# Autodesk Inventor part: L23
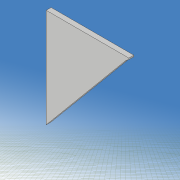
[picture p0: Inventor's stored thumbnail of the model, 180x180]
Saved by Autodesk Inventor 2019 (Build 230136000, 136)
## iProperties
Created: 2021-05
Part Number: L23
Material: 一般
Document SubType Name: Modeling
Designer: kikut
Density: 1 g/cm^3
Appearance: 既定
Mass: 0.00934248 g
Surface Area: 0.426451 cm^2
Volume: 0.00934248 cm^3
Author: kikut
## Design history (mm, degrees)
sketch "スケッチ1"
  geometry: L1 (80, 60)-(-80, 60); L2 (-80, 60)-(-80, -60); L3 (-80, -60)-(80, -60); L4 (80, -60)-(80, 60); L5 (80, 60)-(-80, -60); L6 (-80, 60)-(80, -60); 1 further point
  constraints: 12 end point, 2 midpoint, 2 parallel, 1 horizontal, 1 perpendicular
  dimensions: "d0" = 160 distance of L2.end L3.end; "d1" = 120 distance of L1.end L2.end
extrude "押し出し1" new body sketch "スケッチ1" stored distance "d2" = 0.6; taper "d3" = 0 deg
sketch "スケッチ2"
  geometry: L1 (-140, 0)-(140, 0) reference; L2 (0, -54)-(20, -30); L3 (0, 54)-(20, 30); L4 (0, -3)-(6.514, -3); L5 (6.514, -3)-(16, -6); L6 (16, -6)-(24, -3); L7 (24, -3)-(33.716, -3); L8 (0, 3)-(6.514, 3); L9 (6.514, 3)-(16, 6); L10 (16, 6)-(24, 3); L11 (24, 3)-(33.716, 3); L12 (0, -98)-(0, 98) reference; L13 (-100, -70)-(100, -70); L14 (100, -70)-(100, 70); L15 (100, 70)-(-100, 70); L16 (-100, 70)-(-100, -70); L17 (-100, -70)-(100, 70); L18 (100, -70)-(-100, 70); A1 r 60 centre (54.312, 28.5) between (0, 54) and (0, 3); A2 r 60 centre (54.312, -28.5) between (0, -3) and (0, -54); A3 r 18.111 centre (18, -12) between (20, -30) and (33.716, -3); A4 r 18.111 centre (18, 12) between (33.716, 3) and (20, 30); 1 further point
  constraints: 32 end point, 8 point on circle, 8 symmetric about line, 4 centre point, 3 horizontal, 2 collinear, 2 midpoint, 2 parallel, 1 perpendicular
  dimensions: "d5" = 60 radius of A1; "d6" = 6 distance of L8.start L4.start; "d7" = 108 distance of L3.start L2.start; "d8" = 0 horizontal distance of L3.start L8.start; "d9" = 60 distance of L3.end L2.end; "d10" = 0 horizontal distance of point (0, 0) L3.start; "d11" = 20 horizontal distance of L3.start L3.end; "d12" = 24 distance of A4.centre A3.centre; "d13" = 6 distance of L11.end L7.end; "d14" = 12 distance of L9.end L5.end; "d15" = 16 distance from line of L12 L5.end; "d16" = 24 distance from line of L6.end L12; "d17" = 200 distance of L14.end L15.end; "d18" = 140 distance of L15.end L13.start; "d30" = 18 distance from line of L12 A4.centre
extrude "押し出し2" cut sketch "スケッチ2" stored distance "d19" = 10; taper "d20" = 0 deg
sketch "スケッチ3"
  geometry: L1 (49.705, -17.97)-(33.948, -15.191); L2 (33.948, -15.191)-(34.295, -13.222); L3 (34.295, -13.222)-(50.052, -16); L4 (50.052, -16)-(49.705, -17.97); L5 (49.705, -17.97)-(34.295, -13.222); L6 (33.948, -15.191)-(50.052, -16); L7 (50.052, 16)-(34.295, 13.222); L8 (34.295, 13.222)-(33.948, 15.191); L9 (33.948, 15.191)-(49.705, 17.97); L10 (49.705, 17.97)-(50.052, 16); L11 (50.052, 16)-(33.948, 15.191); L12 (34.295, 13.222)-(49.705, 17.97); L13 (-112, 0)-(112, 0) reference; L14 (0, -84)-(0, 84) reference; 3 further points
  constraints: 24 end point, 4 midpoint, 4 parallel, 2 perpendicular, 2 symmetric about line
  dimensions: "d21" = 2 distance of L3.end L1.start; "d22" = 2 distance of L9.end L7.start; "d23" = 16 distance of L8.end L9.end; "d24" = 42 distance from line of L14 point (42, 15.596); "d26" = 10 deg angle of L7 L13; "d62" = 16 distance from line of L3.end L13
extrude "押し出し3" join sketch "スケッチ3" distance "d27" = 0.6; taper "d28" = 0 deg
fillet "フィレット1" dims "d31" = 2
fillet "フィレット2" dims "d32" = 1
sketch "スケッチ7"
  geometry: L1 (-20, 60)-(80, 60); L2 (80, 60)-(80, -60); L3 (80, -60)-(-20, -60); L4 (-20, -60)-(-20, 60); L5 (0, -82.207)-(0, 85.793) reference; L6 (-40, 0)-(100, 0) reference; L7 (10, -30)-(20, -30); L8 (20, -30)-(20, -46); L9 (20, -46)-(10, -46); L10 (10, -46)-(10, -30); 1 further point
  constraints: 16 end point, 4 parallel, 2 horizontal, 2 perpendicular, 1 other
  dimensions: "d80" = 120 distance of L3.end L1.start; "d81" = 20 distance between parallel lines of L5 L4; "d82" = 100 distance of L1.start L1.end; "d84" = 10 distance of L8.end L9.end; "d85" = 16 distance of L7.end L8.end; "d86" = 30 distance between parallel lines of L4 L10; "d92" = 30 distance between parallel lines of L7 L6
extrude "押し出し5" cut sketch "スケッチ7" stored distance "d87" = 10; taper "d88" = 0 deg
node "ソリッド1"
